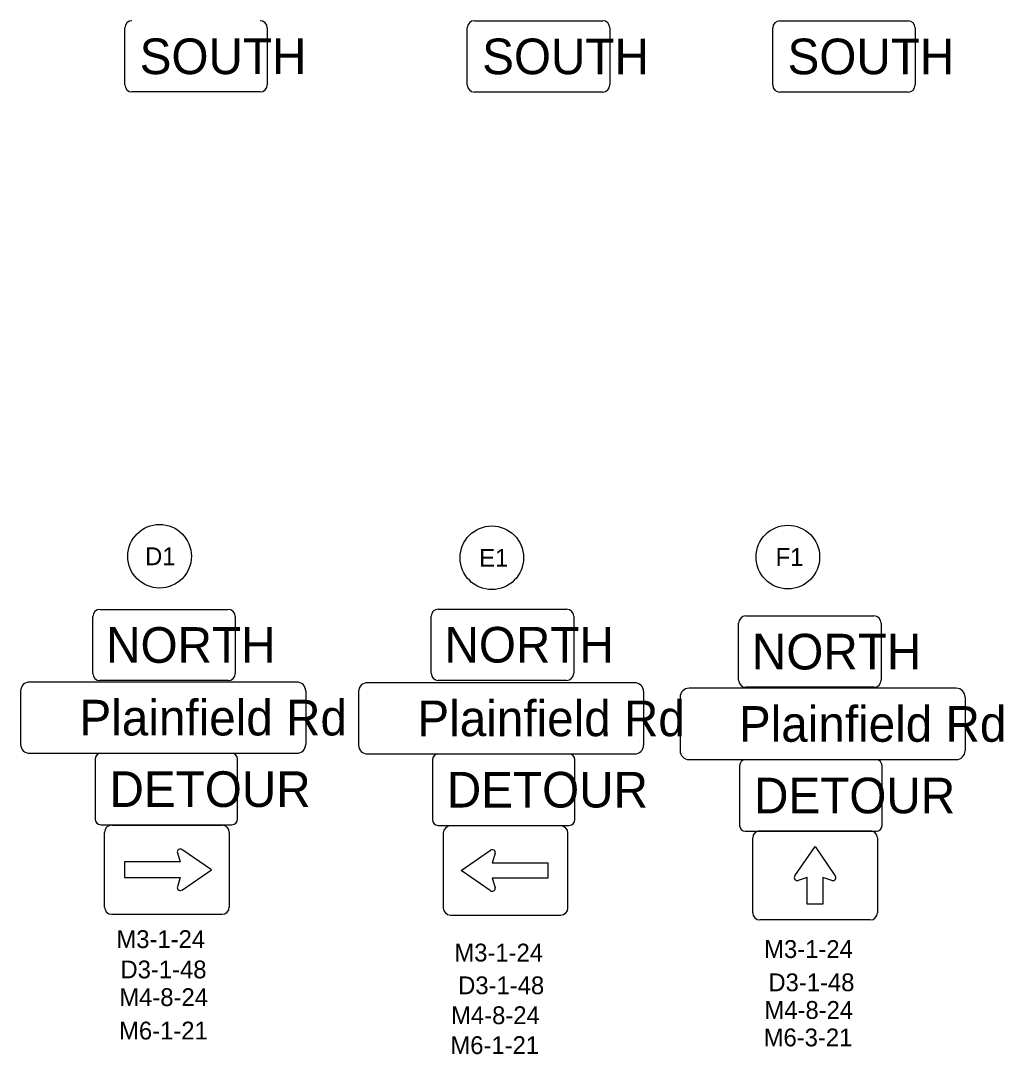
# Model space of a CAD drawing. Extents: x 0 to 42, y 0 to 22.
# Drawn here: x 35.11 to 42.01, y 7.27 to 14.52 of the extents above; entities that cross this region are included whole.
import ezdxf

# ---------------------------------------------------------------- set-up
doc = ezdxf.new("R2010")
doc.units = 0
for name, color, linetype in [('SH_Text', 7, 'Continuous'), ('SN_P_Signs', 7, 'Continuous'), ('SN_P_Text', 7, 'Continuous')]:
    doc.layers.add(name, color=color, linetype=linetype)

msp = doc.modelspace()

# ---------------------------------------------------------------- linework, layer by layer
at = {"layer": 'SH_Text'}
for centre in [(36.0895, 10.7628), (38.4211, 10.7521), (40.4984, 10.7573)]:
    msp.add_circle(centre, 0.2232, dxfattribs=at)
at = {"layer": 'SN_P_Signs'}
for p, q in [((38.299, 14.5192), (39.199, 14.5192)), ((40.4421, 14.5188), (41.3421, 14.5188)), ((35.8456, 14.0698), (35.8456, 14.4698)), ((36.8456, 14.4698), (36.8456, 14.0698)), ((38.249, 14.0692), (38.249, 14.4692)), ((39.249, 14.4692), (39.249, 14.0692)), ((40.3921, 14.0688), (40.3921, 14.4688)), ((41.3921, 14.4688), (41.3921, 14.0688)), ((36.7956, 14.0198), (35.8956, 14.0198)), ((39.199, 14.0192), (38.299, 14.0192)), ((41.3421, 14.0188), (40.4421, 14.0188)), ((35.6711, 10.3905), (36.5711, 10.3905)), ((38.0455, 10.3921), (38.9455, 10.3921)), ((35.6211, 9.9405), (35.6211, 10.3405)), ((36.6211, 10.3405), (36.6211, 9.9405)), ((37.9955, 9.9421), (37.9955, 10.3421)), ((38.9955, 10.3421), (38.9955, 9.9421)), ((40.2028, 10.3438), (41.1028, 10.3438)), ((40.1528, 9.8938), (40.1528, 10.2938)), ((41.1528, 10.2938), (41.1528, 9.8938)), ((36.5711, 9.8905), (35.6711, 9.8905)), ((38.9455, 9.8921), (38.0455, 9.8921)), ((41.1028, 9.8438), (40.2028, 9.8438)), ((35.7536, 8.8761), (36.5286, 8.8761)), ((38.9054, 8.8711), (38.1304, 8.8711)), ((38.9054, 8.8711), (38.9054, 8.8711)), ((35.7036, 8.3011), (35.7036, 8.8261)), ((36.5786, 8.8261), (36.5786, 8.3011)), ((38.0804, 8.8211), (38.0804, 8.2961)), ((38.9554, 8.2961), (38.9554, 8.8211)), ((40.2517, 8.2621), (40.2517, 8.7871)), ((40.3017, 8.8371), (41.0767, 8.8371)), ((41.1267, 8.7871), (41.1267, 8.2621)), ((36.4536, 8.5636), (36.2467, 8.7058)), ((40.547, 8.5207), (40.6892, 8.7277)), ((40.6892, 8.7277), (40.8289, 8.5237)), ((36.2149, 8.6825), (36.2349, 8.6183)), ((38.2054, 8.5586), (38.4123, 8.7007)), ((38.444, 8.6774), (38.4241, 8.6132)), ((36.2349, 8.6183), (35.8443, 8.6183)), ((35.8443, 8.6183), (35.8443, 8.5089)), ((36.2496, 8.4239), (36.4536, 8.5636)), ((38.4094, 8.4188), (38.2054, 8.5586)), ((38.4241, 8.6132), (38.8147, 8.6132)), ((38.8147, 8.6132), (38.8147, 8.5038)), ((35.8443, 8.5089), (36.2349, 8.5089)), ((36.2349, 8.5089), (36.2149, 8.4448)), ((38.8147, 8.5038), (38.4241, 8.5038)), ((38.4241, 8.5038), (38.444, 8.4397)), ((40.6344, 8.5089), (40.5703, 8.489)), ((40.6344, 8.3214), (40.6344, 8.5089)), ((40.808, 8.489), (40.7438, 8.5089)), ((40.7438, 8.5089), (40.7438, 8.3214)), ((40.7438, 8.3214), (40.6344, 8.3214)), ((36.5286, 8.2511), (35.7536, 8.2511)), ((38.1304, 8.2461), (38.9054, 8.2461)), ((41.0767, 8.2121), (40.3017, 8.2121))]:
    msp.add_line(p, q, dxfattribs=at)
for points in [[(37.0523, 9.8808), (35.1773, 9.8808)], [(39.4234, 9.8758), (37.5484, 9.8758)], [(35.1148, 9.8183), (35.1148, 9.4433)], [(37.1148, 9.8183), (37.1148, 9.4433)], [(37.4859, 9.8133), (37.4859, 9.4383)], [(39.4859, 9.8133), (39.4859, 9.4383)], [(41.6799, 9.8367), (39.8049, 9.8367)], [(39.7424, 9.7742), (39.7424, 9.3992)], [(41.7424, 9.7742), (41.7424, 9.3992)], [(35.1773, 9.3808), (37.0523, 9.3808)], [(36.5966, 9.3793), (35.6766, 9.3793)], [(37.5484, 9.3758), (39.4234, 9.3758)], [(38.9637, 9.3753), (38.0437, 9.3753)], [(35.6366, 9.3393), (35.6366, 8.9193)], [(36.6366, 8.9193), (36.6366, 9.3393)], [(38.0037, 9.3353), (38.0037, 8.9153)], [(39.0037, 8.9153), (39.0037, 9.3353)], [(39.8049, 9.3367), (41.6799, 9.3367)], [(40.1595, 9.2946), (40.1595, 8.8746)], [(41.1195, 9.3346), (40.1995, 9.3346)], [(41.1595, 8.8746), (41.1595, 9.2946)], [(35.6766, 8.8793), (36.5966, 8.8793)], [(38.0437, 8.8753), (38.9637, 8.8753)], [(40.1995, 8.8346), (41.1195, 8.8346)]]:
    msp.add_lwpolyline(points, dxfattribs=at)
for centre, radius, start, end in [((35.8956, 14.4698), 0.05, 90, 180), ((36.7956, 14.4698), 0.05, 0, 90), ((38.299, 14.4692), 0.05, 90, 180), ((39.199, 14.4692), 0.05, 0, 90), ((40.4421, 14.4688), 0.05, 90, 180), ((41.3421, 14.4688), 0.05, 0, 90), ((35.8956, 14.0698), 0.05, 180, 270), ((36.7956, 14.0698), 0.05, 270, 0), ((38.299, 14.0692), 0.05, 180, 270), ((39.199, 14.0692), 0.05, 270, 0), ((40.4421, 14.0688), 0.05, 180, 270), ((41.3421, 14.0688), 0.05, 270, 0), ((35.6711, 10.3405), 0.05, 90, 180), ((36.5711, 10.3405), 0.05, 0, 90), ((38.0455, 10.3421), 0.05, 90, 180), ((38.9455, 10.3421), 0.05, 0, 90), ((40.2028, 10.2938), 0.05, 90, 180), ((41.1028, 10.2938), 0.05, 0, 90), ((35.6711, 9.9405), 0.05, 180, 270), ((36.5711, 9.9405), 0.05, 270, 0), ((38.0455, 9.9421), 0.05, 180, 270), ((38.9455, 9.9421), 0.05, 270, 0), ((35.1773, 9.8183), 0.0625, 90, 180), ((37.0523, 9.8183), 0.0625, 0, 90), ((37.5484, 9.8133), 0.0625, 90, 180), ((39.4234, 9.8133), 0.0625, 0, 90), ((40.2028, 9.8938), 0.05, 180, 270), ((41.1028, 9.8938), 0.05, 270, 0), ((39.8049, 9.7742), 0.0625, 90, 180), ((41.6799, 9.7742), 0.0625, 0, 90), ((35.1773, 9.4433), 0.0625, 180, 270), ((37.0523, 9.4433), 0.0625, 270, 0), ((37.5484, 9.4383), 0.0625, 180, 270), ((39.4234, 9.4383), 0.0625, 270, 0), ((35.6766, 9.3393), 0.04, 90, 180), ((36.5966, 9.3393), 0.04, 0, 90), ((38.0437, 9.3353), 0.04, 90, 180), ((38.9637, 9.3353), 0.04, 0, 90), ((39.8049, 9.3992), 0.0625, 180, 270), ((41.6799, 9.3992), 0.0625, 270, 0), ((40.1995, 9.2946), 0.04, 90, 180), ((41.1195, 9.2946), 0.04, 0, 90), ((35.6766, 8.9193), 0.04, 180, 270), ((36.5966, 8.9193), 0.04, 270, 0), ((35.7536, 8.8262), 0.05, 90, 180), ((36.5286, 8.8262), 0.05, 0, 90), ((38.0437, 8.9153), 0.04, 180, 270), ((38.1304, 8.8211), 0.05, 90, 180), ((38.9054, 8.8211), 0.05, 0, 90), ((38.9637, 8.9153), 0.04, 270, 0), ((40.1995, 8.8746), 0.04, 180, 270), ((41.1195, 8.8746), 0.04, 270, 0), ((40.3017, 8.7871), 0.05, 90, 180), ((41.0767, 8.7871), 0.05, 0, 90), ((36.2349, 8.6887), 0.0209, 55.41122, 197.20461), ((38.4242, 8.6836), 0.0209, 342.79539, 124.58878), ((40.5642, 8.5089), 0.0209, 145.41122, 287.20461), ((40.8142, 8.5089), 0.0209, 252.79539, 45.00956), ((36.2349, 8.4387), 0.0209, 162.79539, 315.00956), ((38.4242, 8.4336), 0.0209, 224.99044, 17.20461), ((35.7536, 8.3012), 0.05, 180, 270), ((36.5286, 8.3012), 0.05, 270, 360), ((38.1304, 8.2961), 0.05, 180, 270), ((38.9054, 8.2961), 0.05, 270, 0), ((40.3017, 8.2621), 0.05, 180, 270), ((41.0767, 8.2621), 0.05, 270, 0)]:
    msp.add_arc(centre, radius, start, end, dxfattribs=at)

# ---------------------------------------------------------------- texts
at = {"layer": 'SH_Text'}
for s, p in [('D1', (35.988, 10.7003)), ('E1', (38.3322, 10.6896)), ('F1', (40.4123, 10.6948))]:
    msp.add_text(s, height=0.125, dxfattribs=at).set_placement(p)
at = {"layer": 'SN_P_Signs'}
for s, p in [('SOUTH', (35.9499, 14.1448)), ('SOUTH', (38.3534, 14.1442)), ('SOUTH', (40.4964, 14.1438)), ('NORTH', (35.7145, 10.0155)), ('NORTH', (38.0888, 10.0171)), ('NORTH', (40.2461, 9.9688)), ('     Plainfield Rd', (35.0631, 9.5058)), ('     Plainfield Rd', (37.4342, 9.5008)), ('     Plainfield Rd', (39.6907, 9.4617)), ('DETOUR', (35.7382, 9.0043)), ('DETOUR', (38.1053, 9.0003)), ('DETOUR', (40.2611, 8.9596))]:
    msp.add_text(s, height=0.25, dxfattribs=at).set_placement(p)
at = {"layer": 'SN_P_Text'}
for s, p in [('M3-1-24', (35.7868, 8.0147)), ('M3-1-24', (40.3321, 7.9449)), ('M3-1-24', (38.1581, 7.9202)), ('D3-1-48', (35.8152, 7.8021)), ('D3-1-48', (40.3617, 7.7116)), ('D3-1-48', (38.1847, 7.6906)), ('M4-8-24', (35.8068, 7.6076)), ('M4-8-24', (40.3341, 7.5178)), ('M4-8-24', (38.1351, 7.4807)), ('M6-1-21', (35.8053, 7.3732)), ('M6-1-21', (38.1303, 7.2709)), ('M6-3-21', (40.3286, 7.3251))]:
    msp.add_text(s, height=0.125, dxfattribs=at).set_placement(p)

doc.saveas('drawing.dxf')
